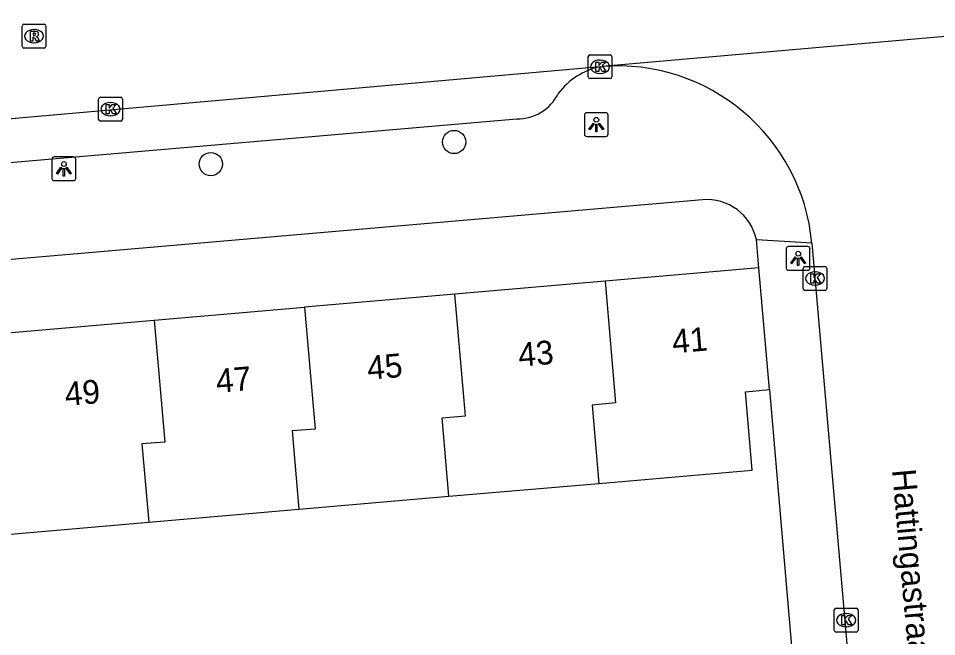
# Model space of a CAD drawing. Extents: x 162990 to 165007, y 383433 to 384336.
# Drawn here: x 164120.2 to 164158.82, y 383812.9 to 383838.9 of the extents above; entities that cross this region are included whole.
import ezdxf

# ---------------------------------------------------------------- set-up
doc = ezdxf.new("R2010")
doc.units = 0
for name, color, linetype in [('IMGEO_Boom', 7, 'Continuous'), ('IMGEO_Kolk', 7, 'Continuous'), ('IMGEO_Lichtpunt', 7, 'Continuous'), ('IMGEO_Openbare_ruimte_label', 7, 'Continuous'), ('IMGEO_Pand', 7, 'Continuous'), ('IMGEO_Pand_nummerreeks', 7, 'Continuous'), ('IMGEO_Rijbaan_lokaal_open', 7, 'Continuous'), ('IMGEO_Rioolput', 7, 'Continuous'), ('IMGEO_Voetpad_open', 7, 'Continuous')]:
    doc.layers.add(name, color=color, linetype=linetype)

msp = doc.modelspace()

# ---------------------------------------------------------------- linework, layer by layer
at = {"layer": 'IMGEO_Boom'}
for centre in [(164138.527, 383833.701), (164128.293, 383832.772)]:
    msp.add_circle(centre, 0.489, dxfattribs=at)
at = {"layer": 'IMGEO_Kolk'}
for p, q in [((164144.24, 383837.365), (164145.092, 383837.365)), ((164144.165, 383836.439), (164144.165, 383837.291)), ((164144.653, 383837.145), (164144.678, 383837.145)), ((164145.166, 383837.291), (164145.166, 383836.439)), ((164144.676, 383836.585), (164144.651, 383836.585)), ((164145.092, 383836.365), (164144.24, 383836.365)), ((164123.575, 383834.654), (164123.575, 383835.506)), ((164123.65, 383835.58), (164124.502, 383835.58)), ((164124.576, 383835.506), (164124.576, 383834.654)), ((164124.063, 383835.36), (164124.088, 383835.36)), ((164124.086, 383834.8), (164124.061, 383834.8)), ((164124.502, 383834.58), (164123.65, 383834.58)), ((164153.281, 383828.46), (164154.133, 383828.46)), ((164153.206, 383827.534), (164153.206, 383828.386)), ((164153.694, 383828.24), (164153.719, 383828.24)), ((164154.207, 383828.386), (164154.207, 383827.534)), ((164153.717, 383827.68), (164153.692, 383827.68)), ((164154.133, 383827.46), (164153.281, 383827.46)), ((164154.515, 383813.169), (164154.515, 383814.021)), ((164154.59, 383814.095), (164155.442, 383814.095)), ((164155.003, 383813.875), (164155.028, 383813.875)), ((164155.516, 383814.021), (164155.516, 383813.169)), ((164155.442, 383813.095), (164154.59, 383813.095)), ((164155.026, 383813.315), (164155.001, 383813.315))]:
    msp.add_line(p, q, dxfattribs=at)
for points in [[(164144.24, 383837.365), (164145.092, 383837.365)], [(164144.165, 383836.439), (164144.165, 383837.291)], [(164144.486, 383837.065), (164144.609, 383837.065), (164144.609, 383836.914), (164144.739, 383837.065), (164144.903, 383837.065), (164144.757, 383836.914), (164144.91, 383836.665), (164144.758, 383836.665), (164144.673, 383836.829), (164144.609, 383836.762), (164144.609, 383836.665), (164144.486, 383836.665), (164144.486, 383837.065)], [(164145.166, 383837.291), (164145.166, 383836.439)], [(164145.092, 383836.365), (164144.24, 383836.365)], [(164123.575, 383834.654), (164123.575, 383835.506)], [(164123.65, 383835.58), (164124.502, 383835.58)], [(164124.576, 383835.506), (164124.576, 383834.654)], [(164123.896, 383835.28), (164124.019, 383835.28), (164124.019, 383835.129), (164124.149, 383835.28), (164124.313, 383835.28), (164124.167, 383835.129), (164124.32, 383834.88), (164124.168, 383834.88), (164124.083, 383835.044), (164124.019, 383834.977), (164124.019, 383834.88), (164123.896, 383834.88), (164123.896, 383835.28)], [(164124.502, 383834.58), (164123.65, 383834.58)], [(164153.281, 383828.46), (164154.133, 383828.46)], [(164153.206, 383827.534), (164153.206, 383828.386)], [(164153.527, 383828.16), (164153.65, 383828.16), (164153.65, 383828.009), (164153.78, 383828.16), (164153.944, 383828.16), (164153.798, 383828.009), (164153.951, 383827.76), (164153.799, 383827.76), (164153.714, 383827.924), (164153.65, 383827.857), (164153.65, 383827.76), (164153.527, 383827.76), (164153.527, 383828.16)], [(164154.207, 383828.386), (164154.207, 383827.534)], [(164154.133, 383827.46), (164153.281, 383827.46)], [(164154.515, 383813.169), (164154.515, 383814.021)], [(164154.59, 383814.095), (164155.442, 383814.095)], [(164154.836, 383813.795), (164154.959, 383813.795), (164154.959, 383813.644), (164155.089, 383813.795), (164155.253, 383813.795), (164155.107, 383813.644), (164155.26, 383813.395), (164155.108, 383813.395), (164155.023, 383813.559), (164154.959, 383813.492), (164154.959, 383813.395), (164154.836, 383813.395), (164154.836, 383813.795)], [(164155.516, 383814.021), (164155.516, 383813.169)], [(164155.442, 383813.095), (164154.59, 383813.095)]]:
    msp.add_lwpolyline(points, dxfattribs=at)
for centre, start, end in [((164144.242, 383837.289), 91.552, 178.448), ((164144.242, 383837.289), 91.552, 178.448), ((164145.09, 383837.289), 1.552, 88.448), ((164145.09, 383837.289), 1.552, 88.448), ((164144.242, 383836.441), 181.552, 268.448), ((164144.242, 383836.441), 181.552, 268.448), ((164145.09, 383836.441), 271.552, 358.448), ((164145.09, 383836.441), 271.552, 358.448), ((164123.652, 383835.504), 91.552, 178.448), ((164123.652, 383835.504), 91.552, 178.448), ((164124.5, 383835.504), 1.552, 88.448), ((164124.5, 383835.504), 1.552, 88.448), ((164123.652, 383834.656), 181.552, 268.448), ((164123.652, 383834.656), 181.552, 268.448), ((164124.5, 383834.656), 271.552, 358.448), ((164124.5, 383834.656), 271.552, 358.448), ((164153.283, 383828.384), 91.552, 178.448), ((164153.283, 383828.384), 91.552, 178.448), ((164154.131, 383828.384), 1.552, 88.448), ((164154.131, 383828.384), 1.552, 88.448), ((164153.283, 383827.536), 181.552, 268.448), ((164153.283, 383827.536), 181.552, 268.448), ((164154.131, 383827.536), 271.552, 358.448), ((164154.131, 383827.536), 271.552, 358.448), ((164154.592, 383814.019), 91.552, 178.448), ((164154.592, 383814.019), 91.552, 178.448), ((164155.44, 383814.019), 1.552, 88.448), ((164155.44, 383814.019), 1.552, 88.448), ((164154.592, 383813.171), 181.552, 268.448), ((164154.592, 383813.171), 181.552, 268.448), ((164155.44, 383813.171), 271.552, 358.448), ((164155.44, 383813.171), 271.552, 358.448)]:
    msp.add_arc(centre, 0.0765, start, end, dxfattribs=at)
for centre, major_axis, ratio, start_param, end_param in [((164144.652, 383836.865), (-0.387, 0.002), 0.722429, 4.712389, 7.853982), ((164144.677, 383836.865), (-0.39, 0.002), 0.717154, 1.570796, 4.712389), ((164124.062, 383835.08), (-0.387, 0.002), 0.722429, 4.712389, 7.853982), ((164124.087, 383835.08), (-0.39, 0.002), 0.717154, 1.570796, 4.712389), ((164153.693, 383827.96), (-0.387, 0.002), 0.722429, 4.712389, 7.853982), ((164153.718, 383827.96), (-0.39, 0.002), 0.717154, 1.570796, 4.712389), ((164155.002, 383813.595), (-0.387, 0.002), 0.722429, 4.712389, 7.853982), ((164155.027, 383813.595), (-0.39, 0.002), 0.717154, 1.570796, 4.712389)]:
    msp.add_ellipse(centre, major_axis=major_axis, ratio=ratio, start_param=start_param, end_param=end_param, dxfattribs=at)
at = {"layer": 'IMGEO_Lichtpunt'}
for p, q in [((164144.009, 383834.836), (164144.009, 383834.029)), ((164144.009, 383834.836), (164144.009, 383834.029)), ((164144.911, 383834.931), (164144.103, 383834.931)), ((164144.911, 383834.931), (164144.103, 383834.931)), ((164145.005, 383834.029), (164145.005, 383834.836)), ((164145.005, 383834.029), (164145.005, 383834.836)), ((164144.103, 383833.935), (164144.911, 383833.935)), ((164144.103, 383833.935), (164144.911, 383833.935)), ((164121.613, 383832.977), (164121.613, 383832.17)), ((164121.613, 383832.977), (164121.613, 383832.17)), ((164122.515, 383833.072), (164121.707, 383833.072)), ((164122.515, 383833.072), (164121.707, 383833.072)), ((164122.609, 383832.17), (164122.609, 383832.977)), ((164122.609, 383832.17), (164122.609, 383832.977)), ((164121.707, 383832.076), (164122.515, 383832.076)), ((164121.707, 383832.076), (164122.515, 383832.076)), ((164153.401, 383829.302), (164152.593, 383829.302)), ((164153.401, 383829.302), (164152.593, 383829.302)), ((164152.499, 383829.207), (164152.499, 383828.4)), ((164152.499, 383829.207), (164152.499, 383828.4)), ((164153.495, 383828.4), (164153.495, 383829.207)), ((164153.495, 383828.4), (164153.495, 383829.207)), ((164152.593, 383828.306), (164153.401, 383828.306)), ((164152.593, 383828.306), (164153.401, 383828.306))]:
    msp.add_line(p, q, dxfattribs=at)
for points in [[(164144.383, 383834.5), (164144.422, 383834.472), (164144.234, 383834.21), (164144.196, 383834.237), (164144.383, 383834.5)], [(164144.485, 383834.452), (164144.532, 383834.452), (164144.532, 383834.13), (164144.485, 383834.13), (164144.485, 383834.452)], [(164144.595, 383834.472), (164144.633, 383834.499), (164144.82, 383834.237), (164144.781, 383834.209), (164144.595, 383834.472)], [(164121.987, 383832.641), (164122.026, 383832.613), (164121.838, 383832.351), (164121.8, 383832.378), (164121.987, 383832.641)], [(164122.089, 383832.593), (164122.136, 383832.593), (164122.136, 383832.271), (164122.089, 383832.271), (164122.089, 383832.593)], [(164122.199, 383832.613), (164122.237, 383832.64), (164122.424, 383832.378), (164122.385, 383832.35), (164122.199, 383832.613)], [(164152.873, 383828.871), (164152.912, 383828.843), (164152.724, 383828.581), (164152.686, 383828.608), (164152.873, 383828.871)], [(164153.085, 383828.843), (164153.123, 383828.87), (164153.31, 383828.608), (164153.271, 383828.58), (164153.085, 383828.843)], [(164152.975, 383828.823), (164153.022, 383828.823), (164153.022, 383828.501), (164152.975, 383828.501), (164152.975, 383828.823)]]:
    msp.add_lwpolyline(points, dxfattribs=at)
for centre in [(164144.508, 383834.634), (164122.112, 383832.775), (164152.998, 383829.005)]:
    msp.add_circle(centre, 0.0994, dxfattribs=at)
for centre, start, end in [((164144.103, 383834.836), 90, 180), ((164144.103, 383834.836), 90, 180), ((164144.911, 383834.836), 0, 90), ((164144.911, 383834.836), 0, 90), ((164144.103, 383834.029), 180, 270), ((164144.103, 383834.029), 180, 270), ((164144.911, 383834.029), 270, 0), ((164144.911, 383834.029), 270, 360), ((164121.707, 383832.977), 90, 180), ((164121.707, 383832.977), 90, 180), ((164122.515, 383832.977), 0, 90), ((164122.515, 383832.977), 0, 90), ((164121.707, 383832.17), 180, 270), ((164121.707, 383832.17), 180, 270), ((164122.515, 383832.17), 270, 0), ((164122.515, 383832.17), 270, 360), ((164152.593, 383829.207), 90, 180), ((164152.593, 383829.207), 90, 180), ((164153.401, 383829.207), 0, 90), ((164153.401, 383829.207), 0, 90), ((164152.593, 383828.4), 180, 270), ((164152.593, 383828.4), 180, 270), ((164153.401, 383828.4), 270, 0), ((164153.401, 383828.4), 270, 360)]:
    msp.add_arc(centre, 0.0946, start, end, dxfattribs=at)
at = {"layer": 'IMGEO_Pand'}
for points in [[(164151.344, 383828.413), (164144.876, 383827.854)], [(164151.788, 383823.289), (164151.344, 383828.413)], [(164144.876, 383827.854), (164138.556, 383827.307)], [(164144.876, 383827.854), (164145.321, 383822.728), (164144.327, 383822.641), (164144.612, 383819.347)], [(164138.556, 383827.307), (164132.235, 383826.76)], [(164138.302, 383818.801), (164138.017, 383822.096), (164139.001, 383822.179), (164138.556, 383827.307)], [(164125.914, 383826.214), (164132.235, 383826.76)], [(164132.235, 383826.76), (164132.68, 383821.631), (164131.708, 383821.55), (164131.993, 383818.256)], [(164119.594, 383825.667), (164125.914, 383826.214)], [(164125.914, 383826.214), (164126.36, 383821.082), (164125.398, 383821.004), (164125.683, 383817.71)], [(164144.612, 383819.347), (164151.068, 383819.906), (164150.783, 383823.202), (164151.788, 383823.289)], [(164138.302, 383818.801), (164144.612, 383819.347)], [(164131.993, 383818.256), (164138.302, 383818.801)], [(164125.683, 383817.71), (164131.993, 383818.256)], [(164119.374, 383817.164), (164125.683, 383817.71)]]:
    msp.add_lwpolyline(points, dxfattribs=at)
at = {"layer": 'IMGEO_Rijbaan_lokaal_open'}
for points in [[(164167.848, 383838.9), (164144.747, 383836.874)], [(164144.669, 383836.867), (164105.622, 383833.417)], [(164144.669, 383836.867), (164144.747, 383836.874)], [(164153.571, 383829.449), (164155.955, 383802.173)]]:
    msp.add_lwpolyline(points, dxfattribs=at)
msp.add_arc((164145.403, 383828.697), 8.203, 5.2571, 94.5846, dxfattribs=at)
at = {"layer": 'IMGEO_Rioolput'}
for p, q in [((164120.357, 383837.726), (164120.357, 383838.578)), ((164120.432, 383838.652), (164121.284, 383838.652)), ((164121.358, 383838.578), (164121.358, 383837.726)), ((164120.845, 383838.432), (164120.87, 383838.432)), ((164120.868, 383837.872), (164120.843, 383837.872)), ((164121.284, 383837.652), (164120.432, 383837.652))]:
    msp.add_line(p, q, dxfattribs=at)
for points in [[(164120.357, 383837.726), (164120.357, 383838.578)], [(164120.432, 383838.652), (164121.284, 383838.652)], [(164121.358, 383838.578), (164121.358, 383837.726)], [(164120.946, 383838.35), (164120.694, 383838.352), (164120.694, 383837.952)], [(164120.694, 383837.952), (164120.818, 383837.952), (164120.818, 383838.114), (164120.829, 383838.114)], [(164120.872, 383838.271), (164120.818, 383838.271), (164120.818, 383838.19)], [(164120.818, 383838.19), (164120.87, 383838.19)], [(164120.876, 383838.085), (164120.947, 383837.952), (164121.087, 383837.952), (164121.022, 383838.078)], [(164121.284, 383837.652), (164120.432, 383837.652)]]:
    msp.add_lwpolyline(points, dxfattribs=at)
for centre, radius, start, end in [((164120.434, 383838.576), 0.0765, 91.552, 178.448), ((164120.434, 383838.576), 0.0765, 91.552, 178.448), ((164121.282, 383838.576), 0.0765, 1.552, 88.448), ((164121.282, 383838.576), 0.0765, 1.552, 88.448), ((164120.828, 383838.061), 0.0533, 26.0293, 88.6989), ((164120.854, 383838.379), 0.19, 274.7715, 282.9687), ((164120.878, 383838.175), 0.0964, 77.0061, 93.1865), ((164120.892, 383838.232), 0.0378, 276.6634, 79.6772), ((164120.945, 383838.24), 0.109, 350.3612, 89.416), ((164120.943, 383838.24), 0.112, 277.5842, 350.9817), ((164120.927, 383838.025), 0.108, 29.5134, 73.7905), ((164120.434, 383837.728), 0.0765, 181.552, 268.448), ((164120.434, 383837.728), 0.0765, 181.552, 268.448), ((164121.282, 383837.728), 0.0765, 271.552, 358.448), ((164121.282, 383837.728), 0.0765, 271.552, 358.448)]:
    msp.add_arc(centre, radius, start, end, dxfattribs=at)
for centre, major_axis, ratio, start_param, end_param in [((164120.844, 383838.152), (-0.387, 0.002), 0.722429, 4.712389, 7.853982), ((164120.869, 383838.152), (-0.39, 0.002), 0.717154, 1.570796, 4.712389)]:
    msp.add_ellipse(centre, major_axis=major_axis, ratio=ratio, start_param=start_param, end_param=end_param, dxfattribs=at)
at = {"layer": 'IMGEO_Voetpad_open'}
for points in [[(164107.12, 383831.741), (164141.171, 383834.669)], [(164148.973, 383831.271), (164100.257, 383827.063)], [(164153.571, 383829.449), (164151.242, 383829.584)], [(164151.344, 383828.413), (164151.242, 383829.584)], [(164151.788, 383823.289), (164155.51, 383779.949)]]:
    msp.add_lwpolyline(points, dxfattribs=at)
for centre, radius, start, end in [((164145.287, 383833.966), 2.966, 102.0205, 143.2919), ((164141.17, 383836.617), 1.948, 270.0311, 333.206), ((164149.15, 383829.14), 2.139, 11.99, 94.7485)]:
    msp.add_arc(centre, radius, start, end, dxfattribs=at)

# ---------------------------------------------------------------- texts
at = {"layer": 'IMGEO_Openbare_ruimte_label'}
msp.add_text('Hattingastraat', height=1, rotation=275.0492, dxfattribs=at).set_placement((164156.942, 383819.911))
at = {"layer": 'IMGEO_Pand_nummerreeks'}
for s, p in [('41', (164147.737, 383824.809)), ('43', (164141.265, 383824.249)), ('45', (164134.907, 383823.699)), ('47', (164128.549, 383823.149)), ('49', (164122.191, 383822.599))]:
    msp.add_text(s, height=1, rotation=4.9428, dxfattribs=at).set_placement(p)

doc.saveas('drawing.dxf')
